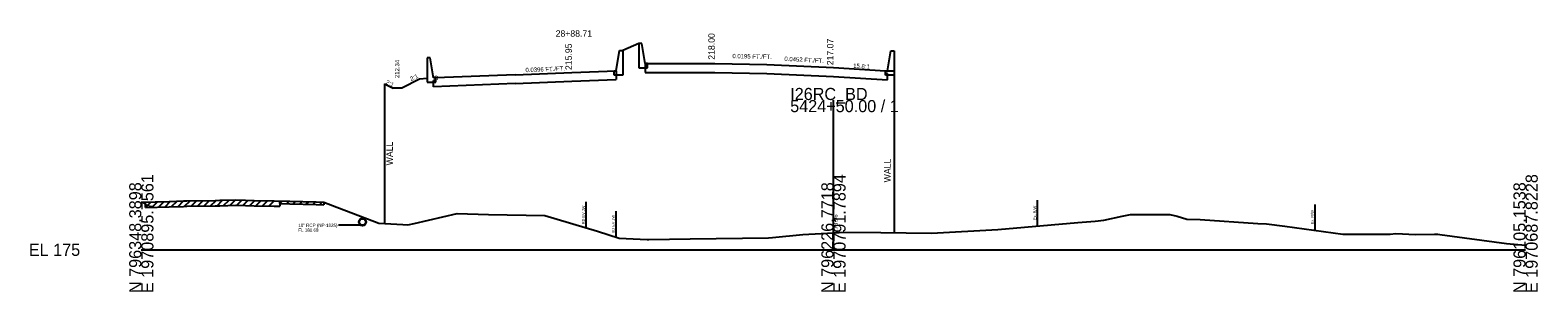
# Model space of a CAD drawing. Extents: x -1417 to 1970873, y -510 to 796304.
# Drawn here: x -1417.4 to -1068.8, y -9.7 to 50.7 of the extents above; entities that cross this region are included whole.
import ezdxf

# ---------------------------------------------------------------- set-up
doc = ezdxf.new("R2010")
doc.units = 0
for name, color, linetype in [('RD_EX_BldgApp', 7, 'Continuous'), ('RD_EX_Conc', 7, 'Continuous'), ('RD_EX_RailRoad', 7, 'Continuous'), ('RD_HC_Cl', 7, 'Continuous'), ('RD_HC_Data', 7, 'Continuous'), ('RD_HC_Data_Tic', 7, 'Continuous'), ('RD_HC_Data_Tic_Rel', 7, 'Continuous'), ('RD_HC_TX_Sta50', 7, 'Continuous'), ('RD_PD_ALT1_LnLine', 7, 'Continuous'), ('RD_PD_ALT1_TrvlWay', 7, 'Continuous'), ('RD_PD_ALT3_CL', 7, 'Continuous'), ('RD_PD_ALT5_CL', 7, 'Continuous'), ('RD_PD_Final_Cl', 7, 'Continuous'), ('RD_PD_Final_LnLine', 7, 'Continuous'), ('RD_PD_Final_TrvlWay', 7, 'Continuous'), ('RD_PD_PaveShd', 7, 'Continuous'), ('RD_SHT_IplotShp', 7, 'Continuous'), ('RD_Sketch2', 7, 'Continuous'), ('RD_Sketch8', 7, 'Continuous'), ('RD_TX_RoadID', 7, 'Continuous')]:
    doc.layers.add(name, color=color, linetype=linetype)

msp = doc.modelspace()

# ---------------------------------------------------------------- linework, layer by layer
at = {"layer": 'RD_EX_Conc'}
for p, q in [((-1281.89, 41.35), (-1281.14, 46.02)), ((-1281.14, 46.02), (-1280.39, 46.02)), ((-1276.69, 47.67), (-1280.39, 46.02)), ((-1280.39, 46.02), (-1280.39, 40.35)), ((-1275.94, 47.67), (-1276.69, 47.67)), ((-1276.69, 47.67), (-1276.69, 42)), ((-1275.19, 43), (-1275.94, 47.67)), ((-1219.17, 41.31), (-1218.42, 45.98)), ((-1218.42, 45.98), (-1217.67, 45.98)), ((-1217.67, 45.98), (-1217.67, 40.31)), ((-1324.86, 44.37), (-1325.61, 44.37)), ((-1325.61, 44.37), (-1325.61, 38.7)), ((-1324.11, 39.7), (-1324.86, 44.37)), ((-1276.69, 42), (-1274.69, 42)), ((-1274.69, 43), (-1275.19, 43)), ((-1274.69, 42), (-1274.69, 43)), ((-1325.61, 38.7), (-1323.61, 38.7)), ((-1323.61, 39.7), (-1324.11, 39.7)), ((-1323.61, 38.7), (-1323.61, 39.7)), ((-1282.39, 40.35), (-1282.39, 41.35)), ((-1282.39, 41.35), (-1281.89, 41.35)), ((-1280.39, 40.35), (-1282.39, 40.35)), ((-1219.67, 40.31), (-1219.67, 41.31)), ((-1219.67, 41.31), (-1219.17, 41.31)), ((-1217.67, 40.31), (-1219.67, 40.31))]:
    msp.add_line(p, q, dxfattribs=at)
at = {"layer": 'RD_HC_Cl'}
for p, q in [((-1231.67, 0), (-1231.67, 34.59)), ((-1391.67, 0), (-1231.67, 0)), ((-1231.67, 0), (-1071.67, 0))]:
    msp.add_line(p, q, dxfattribs=at)
at = {"layer": 'RD_HC_Data'}
for p, q in [((-1390.67, 9.81), (-1390.67, 11.06)), ((-1359.66, 11.3), (-1359.66, 10.05)), ((-1359.66, 10.68), (-1359.66, 11.3)), ((-1359.66, 10.68), (-1357.35, 10.63)), ((-1357.35, 10.63), (-1351.23, 10.45)), ((-1349.45, 11.02), (-1349.45, 10.4)), ((-1390.67, 9.81), (-1385.21, 9.95)), ((-1385.21, 9.95), (-1381.95, 10.04)), ((-1381.95, 10.04), (-1381.11, 10.06)), ((-1381.11, 10.06), (-1374.61, 10.17)), ((-1374.61, 10.17), (-1373.54, 10.19)), ((-1373.54, 10.19), (-1369.83, 10.28)), ((-1369.83, 10.28), (-1367.59, 10.21)), ((-1367.59, 10.21), (-1365.6, 10.17)), ((-1365.6, 10.17), (-1360.95, 10.08)), ((-1360.95, 10.08), (-1359.66, 10.05)), ((-1351.23, 10.45), (-1349.45, 10.4))]:
    msp.add_line(p, q, dxfattribs=at)
at = {"layer": 'RD_HC_Data_Tic_Rel'}
for p, q in [((-1335.48, 38.34), (-1333.48, 37.34)), ((-1327.36, 39.4), (-1331.48, 37.34)), ((-1325.61, 39.54), (-1327.36, 39.4)), ((-1331.48, 37.34), (-1333.48, 37.34))]:
    msp.add_line(p, q, dxfattribs=at)
at = {"layer": 'RD_HC_TX_Sta50'}
for p, q in [((-1390.67, 9.81), (-1389.39, 11.1)), ((-1389.17, 9.85), (-1387.89, 11.13)), ((-1387.67, 9.89), (-1386.39, 11.17)), ((-1386.17, 9.93), (-1384.89, 11.21)), ((-1384.67, 9.97), (-1383.39, 11.25)), ((-1383.17, 10.01), (-1381.89, 11.29)), ((-1381.67, 10.05), (-1380.4, 11.32)), ((-1380.17, 10.08), (-1378.9, 11.35)), ((-1378.67, 10.1), (-1377.4, 11.38)), ((-1377.17, 10.13), (-1375.9, 11.4)), ((-1375.67, 10.16), (-1374.4, 11.43)), ((-1374.17, 10.18), (-1372.9, 11.45)), ((-1372.67, 10.21), (-1371.39, 11.49)), ((-1371.17, 10.25), (-1369.89, 11.53)), ((-1369.67, 10.27), (-1368.46, 11.49)), ((-1368.17, 10.23), (-1366.95, 11.45)), ((-1366.67, 10.19), (-1365.45, 11.41)), ((-1365.17, 10.16), (-1363.94, 11.38)), ((-1363.67, 10.13), (-1362.44, 11.36)), ((-1362.17, 10.1), (-1360.94, 11.33)), ((-1359.66, 10.68), (-1359.04, 11.29)), ((-1358.13, 10.65), (-1357.51, 11.26)), ((-1356.6, 10.61), (-1355.98, 11.21)), ((-1355.07, 10.56), (-1354.45, 11.17)), ((-1353.54, 10.51), (-1352.92, 11.12)), ((-1352, 10.47), (-1351.39, 11.08)), ((-1350.47, 10.43), (-1349.85, 11.03))]:
    msp.add_line(p, q, dxfattribs=at)
at = {"layer": 'RD_PD_ALT1_LnLine'}
for p, q in [((-1184.54, 11.5), (-1184.54, 5.5)), ((-1120.39, 10.49), (-1120.39, 4.49))]:
    msp.add_line(p, q, dxfattribs=at)
at = {"layer": 'RD_PD_ALT1_TrvlWay'}
for p, q in [((-1288.89, 11.08), (-1288.89, 5.08)), ((-1282, 8.94), (-1282, 2.94))]:
    msp.add_line(p, q, dxfattribs=at)
at = {"layer": 'RD_PD_Final_Cl'}
msp.add_lwpolyline([(-1391.67, 11.04), (-1385.21, 11.2), (-1381.95, 11.29), (-1381.11, 11.31), (-1374.61, 11.42), (-1373.54, 11.44), (-1369.83, 11.53), (-1367.59, 11.46), (-1365.6, 11.42), (-1360.95, 11.33), (-1357.35, 11.26), (-1351.23, 11.07), (-1349.45, 11.02), (-1347.51, 10.25), (-1336.75, 6.16), (-1331.2, 5.84), (-1330.04, 5.79), (-1328.59, 6.07), (-1318.66, 8.39), (-1311.39, 8.19), (-1298.37, 7.93), (-1286.22, 4.28), (-1281.17, 2.68), (-1274.76, 2.4), (-1274.36, 2.41), (-1264.77, 2.52), (-1246.7, 2.75), (-1245.74, 2.84), (-1238.75, 3.56), (-1231.67, 3.96), (-1230.35, 4.04), (-1229.28, 4.08), (-1220.69, 3.99), (-1208.97, 3.86), (-1193.67, 4.71), (-1175.2, 6.3), (-1171.19, 6.65), (-1169.15, 6.87), (-1164.94, 7.77), (-1163.01, 8.18), (-1159.88, 8.18), (-1153.89, 8.19), (-1152.19, 7.74), (-1149.95, 7.1), (-1146.88, 6.97), (-1133.56, 6.11), (-1131.58, 5.98), (-1127.35, 5.45), (-1113.92, 3.61), (-1110.78, 3.61), (-1102.94, 3.62), (-1101.68, 3.74), (-1097.09, 3.57), (-1092.72, 3.64), (-1091.96, 3.64), (-1091.49, 3.54), (-1076.06, 1.44), (-1071.67, 1.09)], dxfattribs=at)
at = {"layer": 'RD_PD_Final_LnLine'}
for p, q in [((-1275.19, 43), (-1259.11, 43)), ((-1231.67, 42.07), (-1219.67, 41.31)), ((-1305.21, 40.43), (-1323.61, 39.7)), ((-1292.15, 40.95), (-1281.89, 41.35))]:
    msp.add_line(p, q, dxfattribs=at)
at = {"layer": 'RD_PD_Final_TrvlWay'}
for p, q in [((-1275.19, 43), (-1275.19, 40.96)), ((-1323.61, 39.14), (-1324.13, 39.12)), ((-1324.13, 37.64), (-1324.13, 39.12)), ((-1305.21, 38.39), (-1324.13, 37.64)), ((-1323.61, 39.14), (-1323.61, 39.7)), ((-1305.21, 38.39), (-1292.15, 38.91)), ((-1292.15, 38.91), (-1281.89, 39.31)), ((-1281.89, 41.35), (-1281.89, 39.31)), ((-1275.19, 40.96), (-1259.11, 40.96)), ((-1259.11, 40.96), (-1247.06, 40.73)), ((-1247.06, 40.73), (-1231.67, 40.03)), ((-1231.67, 40.03), (-1219.17, 39.24)), ((-1219.67, 40.75), (-1219.67, 41.31)), ((-1219.17, 40.72), (-1219.67, 40.75)), ((-1219.17, 39.24), (-1219.17, 40.72))]:
    msp.add_line(p, q, dxfattribs=at)
at = {"layer": 'RD_PD_PaveShd'}
for p, q in [((-1259.11, 43), (-1247.06, 42.77)), ((-1247.06, 42.77), (-1231.67, 42.07)), ((-1305.21, 40.43), (-1292.15, 40.95))]:
    msp.add_line(p, q, dxfattribs=at)
at = {"layer": 'RD_SHT_IplotShp'}
msp.add_line((-1341.05, 5.68), (-1346.05, 5.68), dxfattribs=at)
for radius in [0.85, 0.75]:
    msp.add_circle((-1340.55, 6.43), radius, dxfattribs=at)
at = {"layer": 'RD_TX_RoadID'}
for p, q in [((-1219.67, 41.31), (-1217.67, 41.31)), ((-1217.67, 41.31), (-1217.67, 3.95)), ((-1335.47, 38.34), (-1335.47, 6.08))]:
    msp.add_line(p, q, dxfattribs=at)

# ---------------------------------------------------------------- texts
at = {"layer": 'RD_EX_BldgApp'}
msp.add_text('178.96', height=1, rotation=90, dxfattribs=at).set_placement((-1230.67, 3.96))
at = {"layer": 'RD_EX_RailRoad'}
for s, rotation, p in [('212.34', 90, (-1332.04, 39.65)), ('0.0396 FT./FT.', 2.269, (-1302.85, 41.02)), ('0.0195 FT./FT.', 358.8808, (-1255.04, 44.26)), ('0.0452 FT./FT.', 356.9184, (-1243.04, 43.63)), ('2:1', 333.4349, (-1335.28, 38.4)), ('2:1', 26.5651, (-1329.26, 38.93))]:
    msp.add_text(s, height=1, rotation=rotation, dxfattribs=at).set_placement(p)
at = {"layer": 'RD_HC_Cl'}
for s, p in [('I26RC_BD', (-1241.67, 34.59)), ('5424+50.00 / 1', (-1241.67, 31.79)), ('EL 175', (-1417.67, -1.4))]:
    msp.add_text(s, height=2.8, dxfattribs=at).set_placement(p)
for s, p in [('N 796348.3898', (-1391.67, -10)), ('E 1970895.7561', (-1388.87, -10)), ('N 796226.7718', (-1231.67, -10)), ('E 1970791.7894', (-1228.87, -10)), ('N 796105.1538', (-1071.67, -10)), ('E 1970687.8228', (-1068.87, -10))]:
    msp.add_text(s, height=2.8, rotation=90, dxfattribs=at).set_placement(p)
at = {"layer": 'RD_HC_Data_Tic'}
for s, p in [(' 218.00', (-1259.11, 43.34)), (' 215.95', (-1292.15, 40.95)), (' 217.07', (-1231.67, 42.07))]:
    msp.add_text(s, height=1.5, rotation=90, dxfattribs=at).set_placement(p)
at = {"layer": 'RD_PD_ALT1_LnLine'}
for p in [(-1184.79, 6.88), (-1120.64, 5.88)]:
    msp.add_text('Ex. R/W ', height=0.65, rotation=90, dxfattribs=at).set_placement(p)
at = {"layer": 'RD_PD_ALT1_TrvlWay'}
for p in [(-1289.14, 5.91), (-1282.25, 3.78)]:
    msp.add_text('RD EV JW ', height=0.65, rotation=90, dxfattribs=at).set_placement(p)
at = {"layer": 'RD_PD_ALT3_CL'}
msp.add_text('28+88.71', height=1.5, dxfattribs=at).set_placement((-1295.89, 49.2))
at = {"layer": 'RD_PD_ALT5_CL'}
msp.add_text('15.8:1', height=1, rotation=356.3731, dxfattribs=at).set_placement((-1227.14, 42.04))
at = {"layer": 'RD_SHT_IplotShp'}
for s, p in [('18" RCP (NP-1825)', (-1355.38, 5.3)), ('FL 180.68', (-1355.38, 4.18))]:
    msp.add_text(s, height=0.75, dxfattribs=at).set_placement(p)
at = {"layer": 'RD_Sketch2'}
msp.add_text('G', height=1, dxfattribs=at).set_placement((-1324.06, 39.2))
at = {"layer": 'RD_Sketch8'}
for p in [(-1333.52, 19.51), (-1218.46, 15.58)]:
    msp.add_text('WALL', height=1.5, rotation=90, dxfattribs=at).set_placement(p)

doc.saveas('drawing.dxf')
